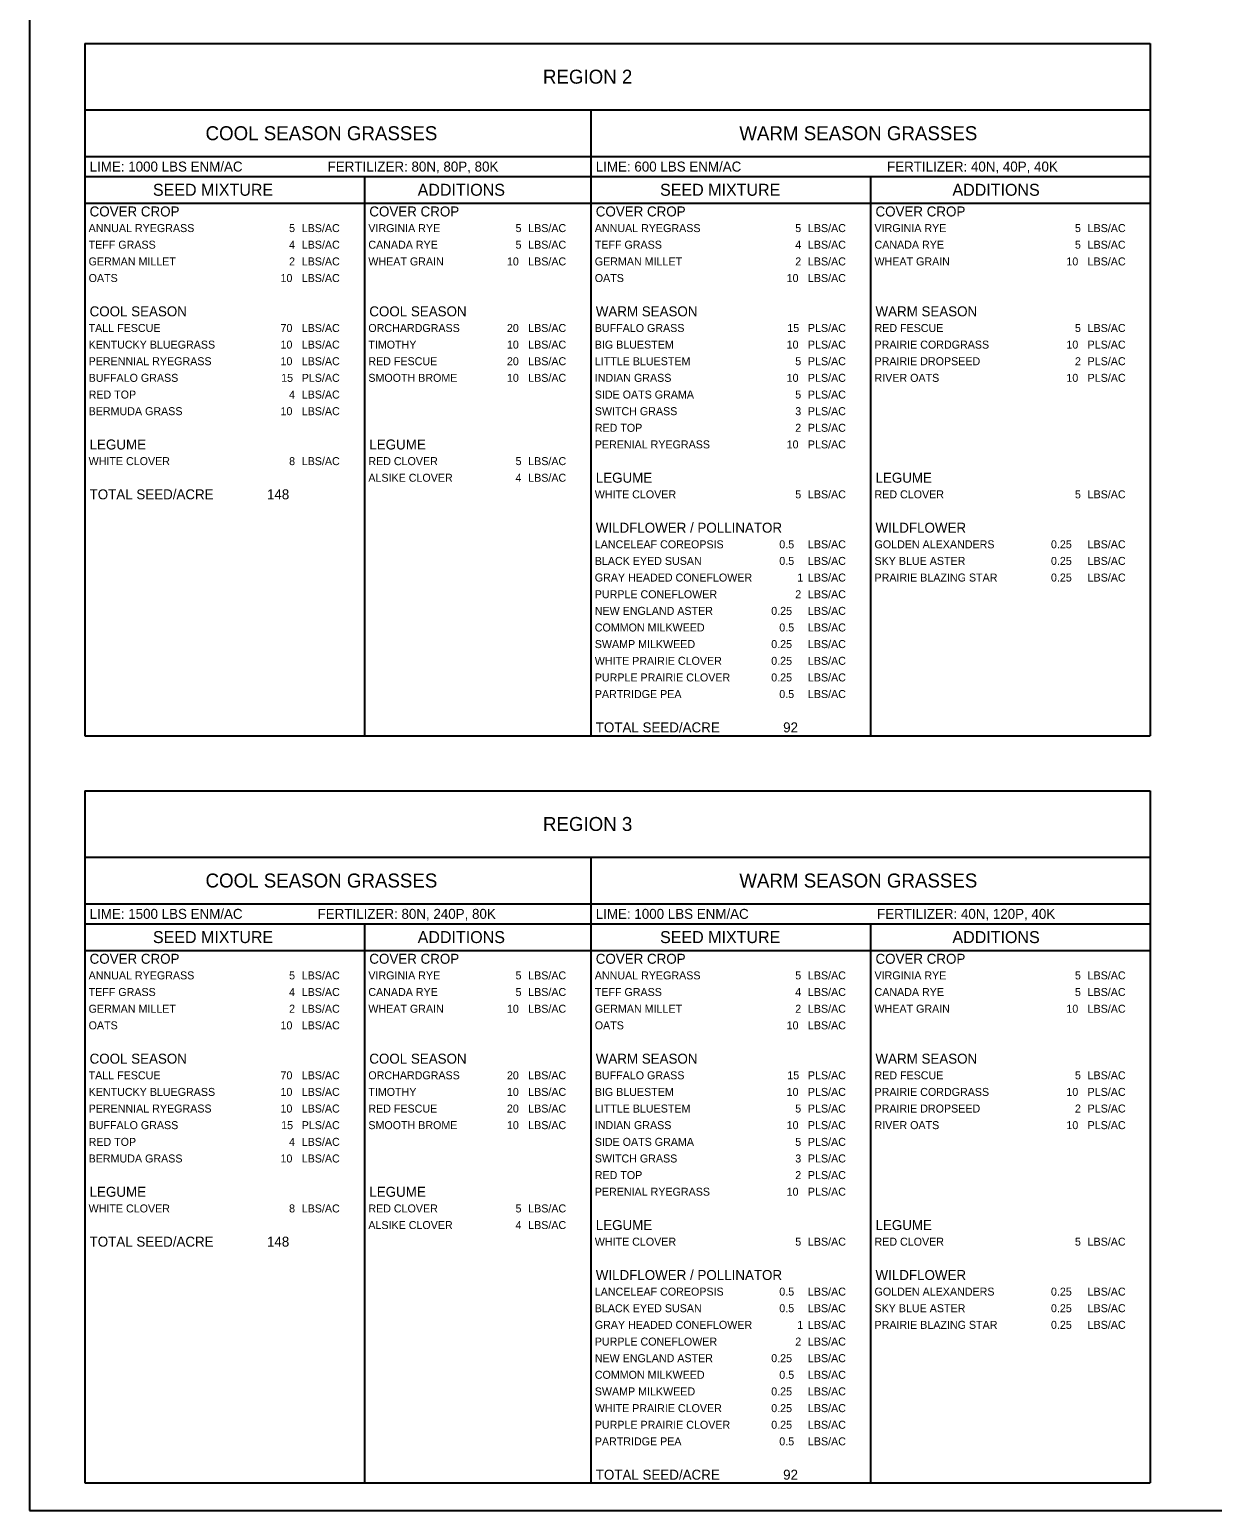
# Model space of a CAD drawing. Extents: x 0 to 3125, y 0 to 2037.
# Drawn here: x 0 to 1074, y 0 to 1346 of the extents above; entities that cross this region are included whole.
import ezdxf

# ---------------------------------------------------------------- set-up
doc = ezdxf.new("R2010")
doc.units = 0
for name, color, linetype in [('Common-Notes', 7, 'Continuous'), ('Draft_Named_Boundary', 7, 'Continuous'), ('Grid_Line-Main', 7, 'Continuous')]:
    doc.layers.add(name, color=color, linetype=linetype)

msp = doc.modelspace()

# ---------------------------------------------------------------- linework, layer by layer
at = {"layer": 'Draft_Named_Boundary'}
msp.add_lwpolyline([(0, 0), (3125, 0), (3125, 2037.5), (0, 2037.5)], close=True, dxfattribs=at)
at = {"layer": 'Grid_Line-Main'}
for p, q in [((50, 1333.3), (1018, 1333.3)), ((50, 1333.3), (50, 704.1)), ((1018, 1333.3), (1018, 704.1)), ((50, 1272.8), (1018, 1272.8)), ((509.8, 1272.8), (509.8, 704.1)), ((50, 1230.4), (1018, 1230.4)), ((50, 1212.3), (1018, 1212.3)), ((304.1, 1212.3), (304.1, 704.1)), ((763.9, 1212.3), (763.9, 704.1)), ((50, 1188.1), (1018, 1188.1)), ((50, 704.1), (1018, 704.1)), ((50, 654.1), (1018, 654.1)), ((50, 654.1), (50, 24.9)), ((1018, 654.1), (1018, 24.9)), ((50, 593.6), (1018, 593.6)), ((509.8, 593.6), (509.8, 24.9)), ((50, 551.2), (1018, 551.2)), ((50, 533.1), (1018, 533.1)), ((304.1, 533.1), (304.1, 24.9)), ((763.9, 533.1), (763.9, 24.9)), ((50, 508.9), (1018, 508.9)), ((50, 24.9), (1018, 24.9))]:
    msp.add_line(p, q, dxfattribs=at)

# ---------------------------------------------------------------- texts
at = {"layer": 'Common-Notes'}
for s, height, p in [(' REGION 2', 12.7, (461.6, 1296.7)), ('COOL SEASON GRASSES', 12.705, (159.8, 1245.3)), ('WARM SEASON GRASSES', 12.705, (644.7, 1245.3)), ('LIME: 1000 LBS ENM/AC', 9.075, (54.5, 1216.8)), ('FERTILIZER: 80N, 80P, 80K', 9.075, (270.7, 1216.8)), ('LIME: 600 LBS ENM/AC', 9.075, (514.3, 1216.8)), ('FERTILIZER: 40N, 40P, 40K', 9.075, (778.9, 1216.8)), ('SEED MIXTURE', 10.89, (112, 1194.8)), ('ADDITIONS ', 10.89, (352.5, 1194.8)), ('SEED MIXTURE', 10.89, (572.7, 1194.8)), ('ADDITIONS ', 10.89, (838.3, 1194.8)), ('COVER CROP', 9.08, (54.5, 1176)), ('COVER CROP', 9.08, (308.6, 1176)), ('COVER CROP', 9.08, (514.3, 1176)), ('COVER CROP', 9.08, (768.4, 1176)), ('ANNUAL RYEGRASS', 7.26, (53.6, 1161.8)), ('5', 7.26, (235.7, 1161.8)), ('LBS/AC', 7.26, (247.2, 1161.8)), ('VIRGINIA RYE', 7.26, (307.7, 1161.8)), ('5', 7.26, (441.4, 1161.8)), ('LBS/AC', 7.26, (452.9, 1161.8)), ('ANNUAL RYEGRASS', 7.26, (513.4, 1161.8)), ('5', 7.26, (695.5, 1161.8)), ('LBS/AC', 7.26, (707, 1161.8)), ('VIRGINIA RYE', 7.26, (767.5, 1161.8)), ('5', 7.26, (949.6, 1161.8)), ('LBS/AC', 7.26, (961.1, 1161.8)), ('TEFF GRASS', 7.26, (53.6, 1146.7)), ('4', 7.26, (235.7, 1146.7)), ('LBS/AC', 7.26, (247.2, 1146.7)), ('CANADA RYE', 7.26, (307.7, 1146.7)), ('5', 7.26, (441.4, 1146.7)), ('LBS/AC', 7.26, (452.9, 1146.7)), ('TEFF GRASS', 7.26, (513.4, 1146.7)), ('4', 7.26, (695.5, 1146.7)), ('LBS/AC', 7.26, (707, 1146.7)), ('CANADA RYE', 7.26, (767.5, 1146.7)), ('5', 7.26, (949.6, 1146.7)), ('LBS/AC', 7.26, (961.1, 1146.7)), ('GERMAN MILLET', 7.26, (53.6, 1131.5)), ('2', 7.26, (235.7, 1131.5)), ('LBS/AC', 7.26, (247.2, 1131.5)), ('WHEAT GRAIN', 7.26, (307.7, 1131.5)), ('10', 7.26, (433.6, 1131.5)), ('LBS/AC', 7.26, (452.9, 1131.5)), ('GERMAN MILLET', 7.26, (513.4, 1131.5)), ('2', 7.26, (695.5, 1131.5)), ('LBS/AC', 7.26, (707, 1131.5)), ('WHEAT GRAIN', 7.26, (767.5, 1131.5)), ('10', 7.26, (941.8, 1131.5)), ('LBS/AC', 7.26, (961.1, 1131.5)), ('OATS', 7.26, (53.6, 1116.4)), ('10', 7.26, (227.9, 1116.4)), ('LBS/AC', 7.26, (247.2, 1116.4)), ('OATS', 7.26, (513.4, 1116.4)), ('10', 7.26, (687.7, 1116.4)), ('LBS/AC', 7.26, (707, 1116.4)), ('COOL SEASON', 9.075, (54.5, 1085.2)), ('COOL SEASON', 9.075, (308.6, 1085.2)), ('WARM SEASON', 9.075, (514.3, 1085.2)), ('WARM SEASON', 9.075, (768.4, 1085.2)), ('TALL FESCUE', 7.26, (53.6, 1071)), ('70', 7.26, (227.9, 1071)), ('LBS/AC', 7.26, (247.2, 1071)), ('ORCHARDGRASS', 7.26, (307.7, 1071)), ('20', 7.26, (433.6, 1071)), ('LBS/AC', 7.26, (452.9, 1071)), ('BUFFALO GRASS', 7.26, (513.4, 1071)), ('15', 7.26, (688.3, 1071)), ('PLS/AC', 7.26, (707, 1071)), ('RED FESCUE', 7.26, (767.5, 1071)), ('5', 7.26, (949.6, 1071)), ('LBS/AC', 7.26, (961.1, 1071)), ('KENTUCKY BLUEGRASS', 7.26, (53.6, 1055.9)), ('10', 7.26, (227.9, 1055.9)), ('LBS/AC', 7.26, (247.2, 1055.9)), ('TIMOTHY', 7.26, (307.7, 1055.9)), ('10', 7.26, (433.6, 1055.9)), ('LBS/AC', 7.26, (452.9, 1055.9)), ('BIG BLUESTEM', 7.26, (513.4, 1055.9)), ('10', 7.26, (687.7, 1055.9)), ('PLS/AC', 7.26, (707, 1055.9)), ('PRAIRIE CORDGRASS', 7.26, (767.5, 1055.9)), ('10', 7.26, (941.8, 1055.9)), ('PLS/AC', 7.26, (961.1, 1055.9)), ('PERENNIAL RYEGRASS', 7.26, (53.6, 1040.8)), ('10', 7.26, (227.9, 1040.8)), ('LBS/AC', 7.26, (247.2, 1040.8)), ('RED FESCUE', 7.26, (307.7, 1040.8)), ('20', 7.26, (433.6, 1040.8)), ('LBS/AC', 7.26, (452.9, 1040.8)), ('LITTLE BLUESTEM', 7.26, (513.4, 1040.8)), ('5', 7.26, (695.5, 1040.8)), ('PLS/AC', 7.26, (707, 1040.8)), ('PRAIRIE DROPSEED', 7.26, (767.5, 1040.8)), ('2', 7.26, (949.6, 1040.8)), ('PLS/AC', 7.26, (961.1, 1040.8)), ('BUFFALO GRASS', 7.26, (53.6, 1025.7)), ('15', 7.26, (228.5, 1025.7)), ('PLS/AC', 7.26, (247.2, 1025.7)), ('SMOOTH BROME', 7.26, (307.7, 1025.7)), ('10', 7.26, (433.6, 1025.7)), ('LBS/AC', 7.26, (452.9, 1025.7)), ('INDIAN GRASS', 7.26, (513.4, 1025.7)), ('10', 7.26, (687.7, 1025.7)), ('PLS/AC', 7.26, (707, 1025.7)), ('RIVER OATS', 7.26, (767.5, 1025.7)), ('10', 7.26, (941.8, 1025.7)), ('PLS/AC', 7.26, (961.1, 1025.7)), ('RED TOP', 7.26, (53.6, 1010.5)), ('4', 7.26, (235.7, 1010.5)), ('LBS/AC', 7.26, (247.2, 1010.5)), ('SIDE OATS GRAMA', 7.26, (513.4, 1010.5)), ('5', 7.26, (695.5, 1010.5)), ('PLS/AC', 7.26, (707, 1010.5)), ('BERMUDA GRASS', 7.26, (53.6, 995.4)), ('10', 7.26, (227.9, 995.4)), ('LBS/AC', 7.26, (247.2, 995.4)), ('SWITCH GRASS', 7.26, (513.4, 995.4)), ('3', 7.26, (695.5, 995.4)), ('PLS/AC', 7.26, (707, 995.4)), ('RED TOP', 7.26, (513.4, 980.3)), ('2', 7.26, (695.5, 980.3)), ('PLS/AC', 7.26, (707, 980.3)), ('LEGUME', 9.08, (54.5, 964.2)), ('LEGUME', 9.08, (308.6, 964.2)), ('PERENIAL RYEGRASS', 7.26, (513.4, 965.2)), ('10', 7.26, (687.7, 965.2)), ('PLS/AC', 7.26, (707, 965.2)), ('WHITE CLOVER', 7.26, (53.6, 950)), ('8', 7.26, (235.7, 950)), ('LBS/AC', 7.26, (247.2, 950)), ('RED CLOVER', 7.26, (307.7, 950)), ('5', 7.26, (441.4, 950)), ('LBS/AC', 7.26, (452.9, 950)), ('ALSIKE CLOVER', 7.26, (307.7, 934.9)), ('4', 7.26, (441.4, 934.9)), ('LBS/AC', 7.26, (452.9, 934.9)), ('LEGUME ', 9.08, (514.3, 934)), ('LEGUME', 9.08, (768.4, 934)), ('TOTAL SEED/ACRE', 9.075, (54.5, 918.9)), ('148', 9.08, (215.6, 918.9)), ('WHITE CLOVER', 7.26, (513.4, 919.8)), ('5', 7.26, (695.5, 919.8)), ('LBS/AC', 7.26, (707, 919.8)), ('RED CLOVER', 7.26, (767.5, 919.8)), ('5', 7.26, (949.6, 919.8)), ('LBS/AC', 7.26, (961.1, 919.8)), ('WILDFLOWER / POLLINATOR ', 9.075, (514.3, 888.6)), ('WILDFLOWER', 9.08, (768.4, 888.6)), ('LANCELEAF COREOPSIS', 7.26, (513.4, 874.4)), ('0.5', 7.26, (681, 874.4)), ('LBS/AC', 7.26, (707, 874.4)), ('GOLDEN ALEXANDERS', 7.26, (767.5, 874.4)), ('0.25', 7.26, (927.8, 874.4)), ('LBS/AC', 7.26, (961.1, 874.4)), ('BLACK EYED SUSAN', 7.26, (513.4, 859.3)), ('0.5', 7.26, (681, 859.3)), ('LBS/AC', 7.26, (707, 859.3)), ('SKY BLUE ASTER', 7.26, (767.5, 859.3)), ('0.25', 7.26, (927.8, 859.3)), ('LBS/AC', 7.26, (961.1, 859.3)), ('GRAY HEADED CONEFLOWER', 7.26, (513.4, 844.2)), ('1', 7.26, (697.3, 844.2)), ('LBS/AC', 7.26, (707, 844.2)), ('PRAIRIE BLAZING STAR', 7.26, (767.5, 844.2)), ('0.25', 7.26, (927.8, 844.2)), ('LBS/AC', 7.26, (961.1, 844.2)), ('PURPLE CONEFLOWER', 7.26, (513.4, 829)), ('2', 7.26, (695.5, 829)), ('LBS/AC', 7.26, (707, 829)), ('NEW ENGLAND ASTER', 7.26, (513.4, 813.9)), ('0.25', 7.26, (673.7, 813.9)), ('LBS/AC', 7.26, (707, 813.9)), ('COMMON MILKWEED', 7.26, (513.4, 798.8)), ('0.5', 7.26, (681, 798.8)), ('LBS/AC', 7.26, (707, 798.8)), ('SWAMP MILKWEED', 7.26, (513.4, 783.7)), ('0.25', 7.26, (673.7, 783.7)), ('LBS/AC', 7.26, (707, 783.7)), ('WHITE PRAIRIE CLOVER', 7.26, (513.4, 768.5)), ('0.25', 7.26, (673.7, 768.5)), ('LBS/AC', 7.26, (707, 768.5)), ('PURPLE PRAIRIE CLOVER', 7.26, (513.4, 753.4)), ('0.25', 7.26, (673.7, 753.4)), ('LBS/AC', 7.26, (707, 753.4)), ('PARTRIDGE PEA', 7.26, (513.4, 738.3)), ('0.5', 7.26, (681, 738.3)), ('LBS/AC', 7.26, (707, 738.3)), ('TOTAL SEED/ACRE', 9.075, (514.3, 707.1)), ('92', 9.08, (684.5, 707.1)), (' REGION 3', 12.7, (461.6, 617.5)), ('COOL SEASON GRASSES', 12.705, (159.8, 566.1)), ('WARM SEASON GRASSES', 12.705, (644.7, 566.1)), ('LIME: 1500 LBS ENM/AC', 9.075, (54.5, 537.6)), ('FERTILIZER: 80N, 240P, 80K', 9.075, (261.6, 537.6)), ('LIME: 1000 LBS ENM/AC', 9.075, (514.3, 537.6)), ('FERTILIZER: 40N, 120P, 40K', 9.075, (769.8, 537.6)), ('SEED MIXTURE', 10.89, (112, 515.6)), ('ADDITIONS ', 10.89, (352.5, 515.6)), ('SEED MIXTURE', 10.89, (572.7, 515.6)), ('ADDITIONS ', 10.89, (838.3, 515.6)), ('COVER CROP', 9.08, (54.5, 496.8)), ('COVER CROP', 9.08, (308.6, 496.8)), ('COVER CROP', 9.08, (514.3, 496.8)), ('COVER CROP', 9.08, (768.4, 496.8)), ('ANNUAL RYEGRASS', 7.26, (53.6, 482.6)), ('5', 7.26, (235.7, 482.6)), ('LBS/AC', 7.26, (247.2, 482.6)), ('VIRGINIA RYE', 7.26, (307.7, 482.6)), ('5', 7.26, (441.4, 482.6)), ('LBS/AC', 7.26, (452.9, 482.6)), ('ANNUAL RYEGRASS', 7.26, (513.4, 482.6)), ('5', 7.26, (695.5, 482.6)), ('LBS/AC', 7.26, (707, 482.6)), ('VIRGINIA RYE', 7.26, (767.5, 482.6)), ('5', 7.26, (949.6, 482.6)), ('LBS/AC', 7.26, (961.1, 482.6)), ('TEFF GRASS', 7.26, (53.6, 467.5)), ('4', 7.26, (235.7, 467.5)), ('LBS/AC', 7.26, (247.2, 467.5)), ('CANADA RYE', 7.26, (307.7, 467.5)), ('5', 7.26, (441.4, 467.5)), ('LBS/AC', 7.26, (452.9, 467.5)), ('TEFF GRASS', 7.26, (513.4, 467.5)), ('4', 7.26, (695.5, 467.5)), ('LBS/AC', 7.26, (707, 467.5)), ('CANADA RYE', 7.26, (767.5, 467.5)), ('5', 7.26, (949.6, 467.5)), ('LBS/AC', 7.26, (961.1, 467.5)), ('GERMAN MILLET', 7.26, (53.6, 452.3)), ('2', 7.26, (235.7, 452.3)), ('LBS/AC', 7.26, (247.2, 452.3)), ('WHEAT GRAIN', 7.26, (307.7, 452.3)), ('10', 7.26, (433.6, 452.3)), ('LBS/AC', 7.26, (452.9, 452.3)), ('GERMAN MILLET', 7.26, (513.4, 452.3)), ('2', 7.26, (695.5, 452.3)), ('LBS/AC', 7.26, (707, 452.3)), ('WHEAT GRAIN', 7.26, (767.5, 452.3)), ('10', 7.26, (941.8, 452.3)), ('LBS/AC', 7.26, (961.1, 452.3)), ('OATS', 7.26, (53.6, 437.2)), ('10', 7.26, (227.9, 437.2)), ('LBS/AC', 7.26, (247.2, 437.2)), ('OATS', 7.26, (513.4, 437.2)), ('10', 7.26, (687.7, 437.2)), ('LBS/AC', 7.26, (707, 437.2)), ('COOL SEASON', 9.075, (54.5, 406)), ('COOL SEASON', 9.075, (308.6, 406)), ('WARM SEASON', 9.075, (514.3, 406)), ('WARM SEASON', 9.075, (768.4, 406)), ('TALL FESCUE', 7.26, (53.6, 391.8)), ('70', 7.26, (227.9, 391.8)), ('LBS/AC', 7.26, (247.2, 391.8)), ('ORCHARDGRASS', 7.26, (307.7, 391.8)), ('20', 7.26, (433.6, 391.8)), ('LBS/AC', 7.26, (452.9, 391.8)), ('BUFFALO GRASS', 7.26, (513.4, 391.8)), ('15', 7.26, (688.3, 391.8)), ('PLS/AC', 7.26, (707, 391.8)), ('RED FESCUE', 7.26, (767.5, 391.8)), ('5', 7.26, (949.6, 391.8)), ('LBS/AC', 7.26, (961.1, 391.8)), ('KENTUCKY BLUEGRASS', 7.26, (53.6, 376.7)), ('10', 7.26, (227.9, 376.7)), ('LBS/AC', 7.26, (247.2, 376.7)), ('TIMOTHY', 7.26, (307.7, 376.7)), ('10', 7.26, (433.6, 376.7)), ('LBS/AC', 7.26, (452.9, 376.7)), ('BIG BLUESTEM', 7.26, (513.4, 376.7)), ('10', 7.26, (687.7, 376.7)), ('PLS/AC', 7.26, (707, 376.7)), ('PRAIRIE CORDGRASS', 7.26, (767.5, 376.7)), ('10', 7.26, (941.8, 376.7)), ('PLS/AC', 7.26, (961.1, 376.7)), ('PERENNIAL RYEGRASS', 7.26, (53.6, 361.6)), ('10', 7.26, (227.9, 361.6)), ('LBS/AC', 7.26, (247.2, 361.6)), ('RED FESCUE', 7.26, (307.7, 361.6)), ('20', 7.26, (433.6, 361.6)), ('LBS/AC', 7.26, (452.9, 361.6)), ('LITTLE BLUESTEM', 7.26, (513.4, 361.6)), ('5', 7.26, (695.5, 361.6)), ('PLS/AC', 7.26, (707, 361.6)), ('PRAIRIE DROPSEED', 7.26, (767.5, 361.6)), ('2', 7.26, (949.6, 361.6)), ('PLS/AC', 7.26, (961.1, 361.6)), ('BUFFALO GRASS', 7.26, (53.6, 346.5)), ('15', 7.26, (228.5, 346.5)), ('PLS/AC', 7.26, (247.2, 346.5)), ('SMOOTH BROME', 7.26, (307.7, 346.5)), ('10', 7.26, (433.6, 346.5)), ('LBS/AC', 7.26, (452.9, 346.5)), ('INDIAN GRASS', 7.26, (513.4, 346.5)), ('10', 7.26, (687.7, 346.5)), ('PLS/AC', 7.26, (707, 346.5)), ('RIVER OATS', 7.26, (767.5, 346.5)), ('10', 7.26, (941.8, 346.5)), ('PLS/AC', 7.26, (961.1, 346.5)), ('RED TOP', 7.26, (53.6, 331.3)), ('4', 7.26, (235.7, 331.3)), ('LBS/AC', 7.26, (247.2, 331.3)), ('SIDE OATS GRAMA', 7.26, (513.4, 331.3)), ('5', 7.26, (695.5, 331.3)), ('PLS/AC', 7.26, (707, 331.3)), ('BERMUDA GRASS', 7.26, (53.6, 316.2)), ('10', 7.26, (227.9, 316.2)), ('LBS/AC', 7.26, (247.2, 316.2)), ('SWITCH GRASS', 7.26, (513.4, 316.2)), ('3', 7.26, (695.5, 316.2)), ('PLS/AC', 7.26, (707, 316.2)), ('RED TOP', 7.26, (513.4, 301.1)), ('2', 7.26, (695.5, 301.1)), ('PLS/AC', 7.26, (707, 301.1)), ('LEGUME', 9.08, (54.5, 285)), ('LEGUME', 9.08, (308.6, 285)), ('PERENIAL RYEGRASS', 7.26, (513.4, 286)), ('10', 7.26, (687.7, 286)), ('PLS/AC', 7.26, (707, 286)), ('WHITE CLOVER', 7.26, (53.6, 270.8)), ('8', 7.26, (235.7, 270.8)), ('LBS/AC', 7.26, (247.2, 270.8)), ('RED CLOVER', 7.26, (307.7, 270.8)), ('5', 7.26, (441.4, 270.8)), ('LBS/AC', 7.26, (452.9, 270.8)), ('ALSIKE CLOVER', 7.26, (307.7, 255.7)), ('4', 7.26, (441.4, 255.7)), ('LBS/AC', 7.26, (452.9, 255.7)), ('LEGUME ', 9.08, (514.3, 254.8)), ('LEGUME', 9.08, (768.4, 254.8)), ('TOTAL SEED/ACRE', 9.075, (54.5, 239.7)), ('148', 9.08, (215.6, 239.7)), ('WHITE CLOVER', 7.26, (513.4, 240.6)), ('5', 7.26, (695.5, 240.6)), ('LBS/AC', 7.26, (707, 240.6)), ('RED CLOVER', 7.26, (767.5, 240.6)), ('5', 7.26, (949.6, 240.6)), ('LBS/AC', 7.26, (961.1, 240.6)), ('WILDFLOWER / POLLINATOR ', 9.075, (514.3, 209.4)), ('WILDFLOWER', 9.08, (768.4, 209.4)), ('LANCELEAF COREOPSIS', 7.26, (513.4, 195.2)), ('0.5', 7.26, (681, 195.2)), ('LBS/AC', 7.26, (707, 195.2)), ('GOLDEN ALEXANDERS', 7.26, (767.5, 195.2)), ('0.25', 7.26, (927.8, 195.2)), ('LBS/AC', 7.26, (961.1, 195.2)), ('BLACK EYED SUSAN', 7.26, (513.4, 180.1)), ('0.5', 7.26, (681, 180.1)), ('LBS/AC', 7.26, (707, 180.1)), ('SKY BLUE ASTER', 7.26, (767.5, 180.1)), ('0.25', 7.26, (927.8, 180.1)), ('LBS/AC', 7.26, (961.1, 180.1)), ('GRAY HEADED CONEFLOWER', 7.26, (513.4, 165)), ('1', 7.26, (697.3, 165)), ('LBS/AC', 7.26, (707, 165)), ('PRAIRIE BLAZING STAR', 7.26, (767.5, 165)), ('0.25', 7.26, (927.8, 165)), ('LBS/AC', 7.26, (961.1, 165)), ('PURPLE CONEFLOWER', 7.26, (513.4, 149.8)), ('2', 7.26, (695.5, 149.8)), ('LBS/AC', 7.26, (707, 149.8)), ('NEW ENGLAND ASTER', 7.26, (513.4, 134.7)), ('0.25', 7.26, (673.7, 134.7)), ('LBS/AC', 7.26, (707, 134.7)), ('COMMON MILKWEED', 7.26, (513.4, 119.6)), ('0.5', 7.26, (681, 119.6)), ('LBS/AC', 7.26, (707, 119.6)), ('SWAMP MILKWEED', 7.26, (513.4, 104.5)), ('0.25', 7.26, (673.7, 104.5)), ('LBS/AC', 7.26, (707, 104.5)), ('WHITE PRAIRIE CLOVER', 7.26, (513.4, 89.3)), ('0.25', 7.26, (673.7, 89.3)), ('LBS/AC', 7.26, (707, 89.3)), ('PURPLE PRAIRIE CLOVER', 7.26, (513.4, 74.2)), ('0.25', 7.26, (673.7, 74.2)), ('LBS/AC', 7.26, (707, 74.2)), ('PARTRIDGE PEA', 7.26, (513.4, 59.1)), ('0.5', 7.26, (681, 59.1)), ('LBS/AC', 7.26, (707, 59.1)), ('TOTAL SEED/ACRE', 9.075, (514.3, 27.9)), ('92', 9.08, (684.5, 27.9))]:
    msp.add_text(s, height=height, dxfattribs=at).set_placement(p)

doc.saveas('drawing.dxf')
